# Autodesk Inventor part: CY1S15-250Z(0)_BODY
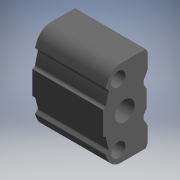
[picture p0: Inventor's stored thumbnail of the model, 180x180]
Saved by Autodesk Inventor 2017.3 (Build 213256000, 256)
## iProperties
Part Number: CY1S15-250Z(0)_BODY
Material: Generic
Catalog Web Link: www.cadenas.de
Description: CY1S-Z_BODY-Magnetically Coupled Rodless Cylinder Slider Type/Slide Bearing
Vendor: SMC
Document SubType Name: Modeling
Designer: partserver
Manufacturer: SMC
Mass: 120.112 g
Surface Area: 247.577 cm^2
Volume: 120.112 cm^3
Density: 1 g/cm^3
Appearance: PSOLRGB-128-128-128
Category: PARTsolutions
Company: SMC
Title: CY1S15-250Z_BODY
Author: Cadenas PARTsolutions
Comments: Magnetically Coupled Rodless Cylinder Slider Type/Slide Bearing
PSOL_IDENT_0: {$CADENAS_DATA\23d-libs\smc_jp\actuator\rodless_cylinders\cy1\cy1s_z\parts\cy1s_z_body.prj},200 {VTY
PSOL_IDENT_1: P=3D},{NB=CY1S15-250Z(0)_BODY},{LINA=CY1S15-250Z_BODY},{NN=CY1S-Z_BODY},{DATE=09.12.2020 02:54:14},{
PSOL_IDENT_2: GEOMDATE=09.03.2020 08:58:35},{VERSION=},{LINEID=30},{WBVAR=STROKE,THREAD2},{WBNUMERIC=STROKE}  {NB=
PSOL_IDENT_3: CY1S15-250Z(0)_BODY},{LINA=CY1S15-250Z_BODY},{KT=DUMMY},{BORE=15},{STROKE=250},{THREAD2=0},{ORDER=CY
PSOL_IDENT_4: 1S15-250Z},{A=7.5},{D=16.6},{D1=12},{E=2.0},{F=38.0},{GP=52},{H=40},{HC=20.500},{HG=15.000},{L=60},{
PSOL_IDENT_5: LD=5.8},{M=8},{MM=M5x0.8},{MMRA=5.000},{MMRP=0.800},{NB1=16.5},{NN=M4x0.7},{PA=30},{PB=50},{PW=76},{
PSOL_IDENT_6: Q=75},{W=73},{A1=50.000},{A2=70.500},{A3=67.000},{A4=10.000},{A5=26.320},{A6=104.000},{A7=48.000},{A
PSOL_IDENT_7: 8=2.000},{A9=0.500},{A10=1.000},{A11=3.500},{A12=1.810},{A13=7.000},{A14=18.900},{A15=12.000},{A16=2
PSOL_IDENT_8: .000},{POS=MIN},{STOP=MIN}
NB: CY1S15-250Z(0)_BODY
NN: M4x0.7
NT: Magnetically Coupled Rodless Cylinder Slider Type/Slide Bearing
NBSYN: $ORDER.($THREAD2.)_BODY
LINA: CY1S15-250Z_BODY
CATALOG: SMC (JP
BORE: 15
STROKE: 250
THREAD2: on
A: 7.5
D: 16.6
D1: 12
E: 2
F: 38
GP: 52
H: 40
HC: 20.5
HG: 15
L: 60
LD: 5.8
M: 8
MM: M5x0.8
MMRA: 5
MMRP: 0.8
NB1: 16.5
PA: 30
PB: 50
PW: 76
Q: 75
W: 73
A1: 50
A2: 70.5
A3: 67
A4: 10
A5: 26.32
A6: 104
A7: 48
A8: 2
A9: 0.5
A10: 1
A11: 3.5
A12: 1.81
A13: 7
A14: 18.9
A15: 12
A16: 2
POS: 0
STOP: 0
SUPPLIER: SMC
ARTICLENO: CY1S15-250Z(0)_BODY
BOMINFO: CY1S15-250Z_BODY
CREATOR: CADENAS GmbH
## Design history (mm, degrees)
sketch "Sketch_8"
  geometry: L1 (38.19, 36.5)-(17.378, 36.5); L2 (4.553, 24.021)-(6.144, 22.588); L3 (3.072, 10.267)-(2.379, 10.095); L4 (2, 9.609)-(2, -9.609); L5 (2.379, -10.095)-(3.072, -10.267); L6 (6.144, -22.588)-(4.553, -24.021); L7 (17.378, -36.5)-(38.19, -36.5); L8 (38.19, -36.5)-(40, -33.365); L9 (40, -33.365)-(40, -20.632); L10 (40, -20.632)-(36.768, -15.034); L11 (36.5, -14.034)-(36.5, -11.866); L12 (36.768, -10.866)-(39, -7); L13 (39, -7)-(39, 7); L14 (39, 7)-(36.768, 10.866); L15 (36.5, 11.866)-(36.5, 14.034); L16 (36.768, 15.034)-(40, 20.632); L17 (40, 20.632)-(40, 33.365); L18 (40, 33.365)-(38.19, 36.5); C1 r 6 at (15, -26); C2 r 8.3 at (20.5, 0); C3 r 6 at (15, 26); A1 r 12 centre (17.378, 24.5) between (17.378, 36.5) and (6.481, 29.526); A2 r 70.5 centre (70.5, 0) between (6.481, 29.526) and (4.419, 24.567); A3 r 0.5 centre (4.888, 24.393) between (4.419, 24.567) and (4.553, 24.021); A4 r 2 centre (4.806, 21.102) between (6.71, 20.491) and (6.144, 22.588); A5 r 67 centre (70.5, 0) between (6.71, 20.491) and (4.557, 11.854); A6 r 2 centre (2.589, 12.208) between (3.072, 10.267) and (4.557, 11.854); A7 r 0.5 centre (2.5, 9.609) between (2.379, 10.095) and (2, 9.609); A8 r 0.5 centre (2.5, -9.609) between (2, -9.609) and (2.379, -10.095); A9 r 2 centre (2.589, -12.208) between (4.557, -11.854) and (3.072, -10.267); A10 r 67 centre (70.5, 0) between (4.557, -11.854) and (6.71, -20.491); A11 r 2 centre (4.806, -21.102) between (6.144, -22.588) and (6.71, -20.491); A12 r 0.5 centre (4.888, -24.393) between (4.553, -24.021) and (4.419, -24.567); A13 r 70.5 centre (70.5, 0) between (4.419, -24.567) and (6.481, -29.526); A14 r 12 centre (17.378, -24.5) between (6.481, -29.526) and (17.378, -36.5); A15 r 2 centre (38.5, -14.034) between (36.5, -14.034) and (36.768, -15.034); A16 r 2 centre (38.5, -11.866) between (36.768, -10.866) and (36.5, -11.866); A17 r 2 centre (38.5, 11.866) between (36.5, 11.866) and (36.768, 10.866); A18 r 2 centre (38.5, 14.034) between (36.768, 15.034) and (36.5, 14.034); 3 further points
  constraints: 36 end point, 36 point on circle, 21 centre point
extrude "Extrusion1" join sketch "Sketch_8" distance "d0" = 60; taper "d1" = 0 deg
sketch "Sketch_2"
  geometry: L1 (15, 30.807)-(15, 40); L2 (15, 40)-(17.5, 40); L3 (17.5, 40)-(17.067, 39.567); L4 (17.067, 39.567)-(17.067, 32); L5 (17.067, 32)-(15, 30.807); L6 (15, 30.807)-(15, 40)
  constraints: 12 end point
revolve "Revolution1" sketch "Sketch_2" stored, may be unused: angle "d2" = 360 deg
thread "Thread1" dims "d3" = 7.567, "d4" = 0
pattern_linear "Rectangular Pattern1" dims "d7" = 30, "d10" = 50
node "BODY_CT_XY"
node "BODY_CT_YZ"
node "BODY_CT_ZX"
node "BODY_CT_X"
node "BODY_CT_Y"
node "BODY_CT_Z"
node "BODY_CT_Center"
body "Solid1"
